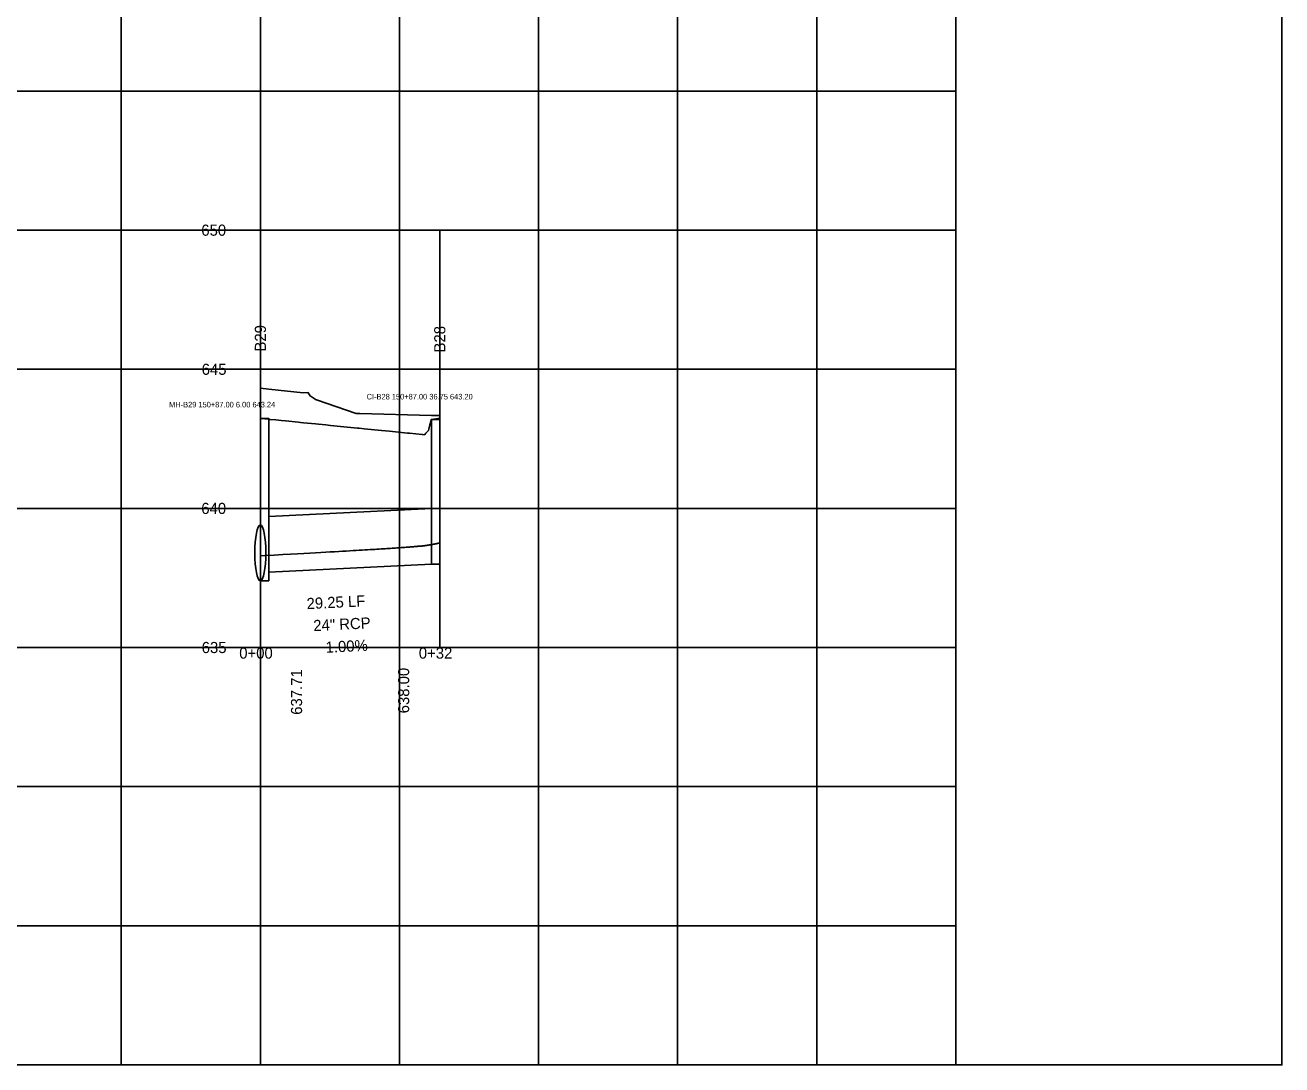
# Model space of a CAD drawing. Extents: x 2253035 to 2279930, y 13774972 to 13793443.
# Drawn here: x 2277907.1 to 2278133, y 13792491.3 to 13792678.1 of the extents above; entities that cross this region are included whole.
import ezdxf

# ---------------------------------------------------------------- set-up
doc = ezdxf.new("R2010")
doc.units = 0
for name, color, linetype in [('Default', 7, 'Continuous'), ('E_Utility_ATT_HH', 7, 'Continuous'), ('E_Utility_ATT_PR_PVC', 7, 'Continuous'), ('E_Utility_Telephone_Manhole Telephone_MHT_point', 7, 'Continuous'), ('E_Utility_Telephone_Telephone Pedestal_TPED_Description', 7, 'Continuous'), ('E_Utility_Water_Water Meter_WM_Description', 7, 'Continuous'), ('E_Utillity_Water_Water Line_12in', 7, 'Continuous'), ('E_Utillity_Water_Water Line_1in', 7, 'Continuous'), ('E_Utillity_Water_Water Line_4in', 7, 'Continuous'), ('E_Utillity_Water_Water Line_8in', 7, 'Continuous')]:
    doc.layers.add(name, color=color, linetype=linetype)

msp = doc.modelspace()

# ---------------------------------------------------------------- linework, layer by layer
at = {"layer": 'Default'}
for p, q in [((2277949.4, 13792616.27), (2277981.65, 13792616.27)), ((2277949.4, 13792591.27), (2277981.65, 13792591.27))]:
    msp.add_line(p, q, dxfattribs=at)
msp.add_lwpolyline([(2277949.4, 13792566.27), (2277949.4, 13792641.27), (2277981.65, 13792641.27), (2277981.65, 13792566.27)], close=True, dxfattribs=at)
at = {"layer": 'E_Utility_ATT_PR_PVC'}
msp.add_lwpolyline([(2277949.4, 13792582.76), (2277950.22, 13792582.81), (2277951.9, 13792582.89), (2277953.42, 13792582.98), (2277954.8, 13792583.05), (2277956.06, 13792583.12), (2277957.23, 13792583.18), (2277958.31, 13792583.24), (2277959.32, 13792583.29), (2277960.26, 13792583.35), (2277961.14, 13792583.4), (2277961.96, 13792583.44), (2277962.74, 13792583.49), (2277963.48, 13792583.53), (2277964.17, 13792583.57), (2277964.83, 13792583.61), (2277965.46, 13792583.64), (2277966.05, 13792583.68), (2277966.62, 13792583.71), (2277967.16, 13792583.74), (2277967.68, 13792583.77), (2277968.18, 13792583.8), (2277968.65, 13792583.83), (2277969.11, 13792583.86), (2277969.54, 13792583.89), (2277969.96, 13792583.91), (2277970.36, 13792583.94), (2277970.75, 13792583.96), (2277971.12, 13792583.99), (2277971.48, 13792584.01), (2277971.83, 13792584.03), (2277972.16, 13792584.05), (2277972.48, 13792584.07), (2277972.79, 13792584.09), (2277973.09, 13792584.11), (2277973.38, 13792584.13), (2277973.66, 13792584.15), (2277973.93, 13792584.17), (2277974.2, 13792584.19), (2277974.45, 13792584.21), (2277974.69, 13792584.22), (2277974.93, 13792584.24), (2277975.16, 13792584.26), (2277975.38, 13792584.27), (2277975.6, 13792584.29), (2277975.81, 13792584.3), (2277976.01, 13792584.32), (2277976.21, 13792584.33), (2277976.4, 13792584.35), (2277976.58, 13792584.36), (2277976.76, 13792584.38), (2277976.94, 13792584.39), (2277977.1, 13792584.4), (2277977.27, 13792584.42), (2277977.43, 13792584.43), (2277977.58, 13792584.44), (2277977.73, 13792584.46), (2277977.88, 13792584.47), (2277978.02, 13792584.48), (2277978.15, 13792584.49), (2277978.29, 13792584.5), (2277978.41, 13792584.51), (2277978.54, 13792584.53), (2277978.66, 13792584.54), (2277978.78, 13792584.55), (2277978.89, 13792584.57), (2277979, 13792584.59), (2277979.11, 13792584.6), (2277979.22, 13792584.62), (2277979.32, 13792584.63), (2277979.42, 13792584.65), (2277979.51, 13792584.66), (2277979.6, 13792584.68), (2277979.69, 13792584.69), (2277979.78, 13792584.7), (2277979.86, 13792584.72), (2277979.95, 13792584.73), (2277980.02, 13792584.74), (2277980.1, 13792584.76), (2277980.17, 13792584.77), (2277980.25, 13792584.78), (2277980.32, 13792584.79), (2277980.38, 13792584.8), (2277980.45, 13792584.82), (2277980.51, 13792584.83), (2277980.57, 13792584.84), (2277980.63, 13792584.85), (2277980.69, 13792584.86), (2277980.74, 13792584.87), (2277980.79, 13792584.88), (2277980.84, 13792584.89), (2277980.89, 13792584.9), (2277980.94, 13792584.91), (2277980.98, 13792584.92), (2277981.03, 13792584.93), (2277981.07, 13792584.94), (2277981.11, 13792584.95), (2277981.15, 13792584.96), (2277981.18, 13792584.96), (2277981.22, 13792584.97), (2277981.25, 13792584.98), (2277981.28, 13792584.99), (2277981.31, 13792585), (2277981.34, 13792585.01), (2277981.37, 13792585.01), (2277981.4, 13792585.02), (2277981.42, 13792585.03), (2277981.44, 13792585.04), (2277981.47, 13792585.04), (2277981.49, 13792585.05), (2277981.51, 13792585.06), (2277981.52, 13792585.06), (2277981.54, 13792585.07), (2277981.56, 13792585.08), (2277981.57, 13792585.08), (2277981.58, 13792585.09), (2277981.6, 13792585.1), (2277981.61, 13792585.1), (2277981.62, 13792585.11), (2277981.62, 13792585.11), (2277981.63, 13792585.12), (2277981.64, 13792585.13), (2277981.64, 13792585.13), (2277981.65, 13792585.14), (2277981.65, 13792585.14), (2277981.65, 13792585.15), (2277981.65, 13792585.15), (2277981.65, 13792585.16), (2277981.65, 13792586.53)], dxfattribs=at)
at = {"layer": 'E_Utility_Telephone_Manhole Telephone_MHT_point'}
for p, q in [((2277924.4, 13792491.27), (2277924.4, 13792791.27)), ((2277949.4, 13792491.27), (2277949.4, 13792791.27)), ((2277974.4, 13792491.27), (2277974.4, 13792791.27)), ((2277999.4, 13792491.27), (2277999.4, 13792791.27)), ((2278024.4, 13792491.27), (2278024.4, 13792791.27)), ((2278049.4, 13792491.27), (2278049.4, 13792791.27)), ((2278074.4, 13792491.27), (2278074.4, 13792791.27)), ((2277749.4, 13792666.27), (2278074.4, 13792666.27)), ((2277749.4, 13792641.27), (2278074.4, 13792641.27)), ((2277749.4, 13792616.27), (2278074.4, 13792616.27)), ((2277749.4, 13792591.27), (2278074.4, 13792591.27)), ((2277749.4, 13792566.27), (2278074.4, 13792566.27)), ((2277749.4, 13792541.27), (2278074.4, 13792541.27)), ((2277749.4, 13792516.27), (2278074.4, 13792516.27)), ((2277749.4, 13792491.27), (2278074.4, 13792491.27))]:
    msp.add_line(p, q, dxfattribs=at)
at = {"layer": 'E_Utility_Water_Water Meter_WM_Description'}
msp.add_lwpolyline([(2278133.03, 13792792.44), (2277749.4, 13792792.44), (2277749.4, 13792491.27), (2278133.03, 13792491.27)], close=True, dxfattribs=at)
at = {"layer": 'E_Utillity_Water_Water Line_12in'}
for points in [[(2277949.4, 13792607.44), (2277950.9, 13792607.44), (2277950.9, 13792578.27), (2277949.4, 13792578.27)], [(2277980.15, 13792607.27), (2277981.65, 13792607.27), (2277981.65, 13792581.27), (2277980.15, 13792581.27)]]:
    msp.add_lwpolyline(points, close=True, dxfattribs=at)
at = {"layer": 'E_Utillity_Water_Water Line_1in'}
msp.add_lwpolyline([(2277949.4, 13792612.88), (2277950.9, 13792612.72), (2277950.9, 13792612.72), (2277957.08, 13792612.06), (2277957.97, 13792612.08), (2277958.02, 13792612.06), (2277958.36, 13792611.49), (2277959.42, 13792610.8), (2277959.42, 13792610.8), (2277959.47, 13792610.77), (2277966.63, 13792608.3), (2277967.29, 13792608.32), (2277980.15, 13792607.99), (2277980.15, 13792607.99), (2277981.65, 13792607.95)], dxfattribs=at)
at = {"layer": 'E_Utillity_Water_Water Line_4in'}
for p, q in [((2277950.9, 13792589.8), (2277980.15, 13792591.27)), ((2277950.9, 13792579.8), (2277980.15, 13792581.27))]:
    msp.add_line(p, q, dxfattribs=at)
msp.add_ellipse((2277949.4, 13792583.27), major_axis=(0, 5), ratio=0.2, dxfattribs=at)
at = {"layer": 'E_Utillity_Water_Water Line_8in'}
msp.add_lwpolyline([(2277949.4, 13792607.44), (2277950.9, 13792607.29), (2277950.9, 13792607.29), (2277951.04, 13792607.28), (2277951.1, 13792607.27), (2277951.16, 13792607.27), (2277952.16, 13792607.17), (2277953.13, 13792607.07), (2277953.9, 13792606.99), (2277956.23, 13792606.76), (2277956.6, 13792606.72), (2277957.17, 13792606.67), (2277959.29, 13792606.45), (2277959.87, 13792606.4), (2277961.16, 13792606.27), (2277961.99, 13792606.18), (2277962.62, 13792606.12), (2277965.02, 13792605.88), (2277965.66, 13792605.82), (2277966.87, 13792605.7), (2277967.17, 13792605.67), (2277968.07, 13792605.58), (2277971.16, 13792605.27), (2277971.87, 13792605.2), (2277972.62, 13792605.12), (2277975.85, 13792604.8), (2277976.23, 13792604.76), (2277978.48, 13792604.54), (2277978.54, 13792604.53), (2277978.9, 13792604.5), (2277978.92, 13792604.52), (2277978.93, 13792604.53), (2277978.95, 13792604.55), (2277978.95, 13792604.55), (2277978.97, 13792604.58), (2277979.14, 13792604.76), (2277979.4, 13792605.03), (2277979.48, 13792605.12), (2277979.54, 13792605.19), (2277979.62, 13792605.27), (2277979.68, 13792605.53), (2277979.87, 13792606.27), (2277980.03, 13792606.86), (2277980.13, 13792607.27), (2277980.15, 13792607.27), (2277980.15, 13792607.27), (2277981.65, 13792607.5)], dxfattribs=at)

# ---------------------------------------------------------------- texts
at = {"layer": 'Default'}
for s, p in [('650', (2277938.78, 13792640.27)), ('645', (2277938.85, 13792615.27)), ('640', (2277938.78, 13792590.27)), ('635', (2277938.85, 13792565.27)), ('0+00', (2277945.6, 13792564.27)), ('0+32', (2277977.88, 13792564.27))]:
    msp.add_text(s, height=2, dxfattribs=at).set_placement(p)
at = {"layer": 'E_Utility_ATT_HH'}
for s, rotation, p in [('B29', 90, (2277950.4, 13792619.46)), ('B28', 90, (2277982.65, 13792619.29)), ('29.25 LF', 2.8624, (2277957.76, 13792573.15)), ('24" RCP', 2.8624, (2277958.96, 13792569.2)), ('1.00%', 2.8624, (2277961.17, 13792565.31)), ('637.71', 90, (2277956.9, 13792554.18)), ('638.00', 90, (2277976.15, 13792554.44))]:
    msp.add_text(s, height=2, rotation=rotation, dxfattribs=at).set_placement(p)
at = {"layer": 'E_Utility_Telephone_Telephone Pedestal_TPED_Description'}
for s, p in [('MH-B29 150+87.00 6.00 643.24', (2277932.99, 13792609.42)), ('CI-B28 150+87.00 36.75 643.20', (2277968.5, 13792610.85))]:
    msp.add_text(s, height=1, rotation=0, dxfattribs=at).set_placement(p)

doc.saveas('drawing.dxf')
